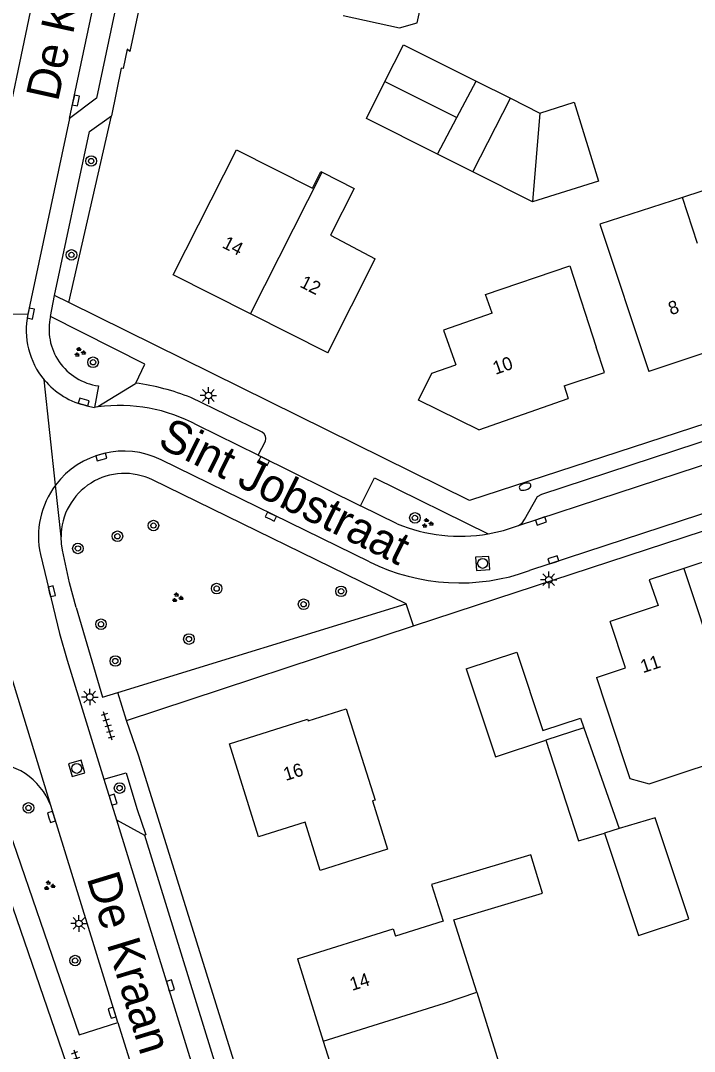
# Model space of a CAD drawing. Extents: x 136000 to 138005, y 398500 to 400500.
# Drawn here: x 137480.9 to 137531.8, y 398977.7 to 399055.6 of the extents above; entities that cross this region are included whole.
import ezdxf

# ---------------------------------------------------------------- set-up
doc = ezdxf.new("R2010")
doc.units = 0
for name, color, linetype in [('gg-anno-huisnummerreeks BGT', 7, 'Continuous'), ('gg-anno-openbare ruimte label', 7, 'Continuous'), ('gg-bbg-bijgebouw', 7, 'Continuous'), ('gg-bbg-gedigitaliseerde bebouwing', 7, 'Continuous'), ('gg-bbg-gedigitaliseerde bijgebouw', 7, 'Continuous'), ('gg-bbg-hoofdgebouw', 7, 'Continuous'), ('gg-bbg-tussenscheiding', 7, 'Continuous'), ('gg-knt-verharding', 7, 'Continuous'), ('gg-knt-verharding nz', 7, 'Continuous'), ('gt-grn-groengrens', 7, 'Continuous'), ('gt-grn-weggrens', 7, 'Continuous'), ('gt-symb-boom', 7, 'Continuous'), ('gt-symb-brandkraan', 7, 'Continuous'), ('gt-symb-groenvak', 7, 'Continuous'), ('gt-symb-kolk', 7, 'Continuous'), ('gt-symb-lichtmast', 7, 'Continuous'), ('gt-symb-rioolschacht', 7, 'Continuous'), ('gt-symb-tegel verharding', 7, 'Continuous')]:
    doc.layers.add(name, color=color, linetype=linetype)

# ---------------------------------------------------------------- blocks, each defined once
blk = doc.blocks.new('gt0-BOOM')
at = {"layer": 'gt-symb-boom'}
for radius in [0.4, 0.2]:
    blk.add_circle((0, 0), radius, dxfattribs=at)
blk = doc.blocks.new('gt0-KOLK')
at = {"layer": 'gt-symb-kolk'}
blk.add_lwpolyline([(0, 0), (0.375, 0), (0.375, 0.4), (-0.375, 0.4), (-0.375, 0), (0, 0)], dxfattribs=at)
blk = doc.blocks.new('gt0-LMAST')
at = {"layer": 'gt-symb-lichtmast'}
for p, q in [((-0.182, 0.173), (-0.447, 0.438)), ((-0.005, 0.246), (-0.005, 0.621)), ((0.172, 0.173), (0.437, 0.438)), ((-0.255, -0.004), (-0.63, -0.004)), ((-0.182, -0.181), (-0.447, -0.446)), ((-0.005, -0.254), (-0.005, -0.629)), ((0.437, -0.446), (0.172, -0.181)), ((0.245, -0.004), (0.62, -0.004))]:
    blk.add_line(p, q, dxfattribs=at)
blk.add_circle((-0.005, -0.004), 0.25, dxfattribs=at)
blk = doc.blocks.new('gt0-GRVAK')
at = {"layer": 'gt-symb-groenvak'}
for p, q in [((-0.11, 0.189), (-0.228, 0.24)), ((-0.182, 0.153), (0.088, 0.153)), ((-0.091, 0.211), (-0.156, 0.322)), ((-0.047, 0.214), (-0.047, 0.393)), ((-0.004, 0.211), (0.061, 0.322)), ((0.015, 0.189), (0.133, 0.24)), ((0.262, -0.052), (0.197, 0.059)), ((0.305, -0.049), (0.305, 0.13)), ((0.349, -0.052), (0.414, 0.059)), ((-0.245, -0.228), (-0.363, -0.177)), ((-0.318, -0.264), (-0.047, -0.264)), ((-0.226, -0.206), (-0.291, -0.095)), ((-0.183, -0.203), (-0.183, -0.024)), ((-0.139, -0.206), (-0.074, -0.095)), ((-0.12, -0.228), (-0.002, -0.177)), ((0.243, -0.074), (0.125, -0.023)), ((0.17, -0.11), (0.441, -0.11)), ((0.368, -0.074), (0.486, -0.023))]:
    blk.add_line(p, q, dxfattribs=at)
blk = doc.blocks.new('gt0-RS')
at = {"layer": 'gt-symb-rioolschacht'}
blk.add_lwpolyline([(-0.5, -0.5), (0.5, -0.5), (0.5, 0.5), (-0.5, 0.5)], close=True, dxfattribs=at)
blk.add_circle((0, 0), 0.375, dxfattribs=at)
blk = doc.blocks.new('gt0-BR')
at = {"layer": 'gt-symb-brandkraan'}
for centre, radius, start, end in [((-0.244, 0), 0.206, 107.56694, 252.43307), ((0.599, -2.664), 3, 106.89205, 107.56694), ((0, -0.691), 0.938, 73.10799, 106.89205), ((-0.599, -2.664), 3, 72.43309, 73.10799), ((0.244, 0), 0.206, 287.56695, 72.43309), ((0.599, 2.664), 3, 252.43307, 253.10797), ((0, 0.691), 0.938, 253.10797, 286.89206), ((-0.599, 2.664), 3, 286.89206, 287.56695)]:
    blk.add_arc(centre, radius, start, end, dxfattribs=at)
blk = doc.blocks.new('gt0-TEG1')
at = {"layer": 'gt-symb-tegel verharding'}
for p, q in [((-1.125, 0), (1.125, 0)), ((-0.9, -0.25), (-0.9, 0.25)), ((-0.45, -0.25), (-0.45, 0.25)), ((0, -0.25), (0, 0.25)), ((0.45, -0.25), (0.45, 0.25)), ((0.9, -0.25), (0.9, 0.25))]:
    blk.add_line(p, q, dxfattribs=at)

msp = doc.modelspace()

# ---------------------------------------------------------------- linework, layer by layer
at = {"layer": 'gg-bbg-bijgebouw'}
msp.add_line((137514.56, 399006.621), (137518.378, 399007.874), dxfattribs=at)
msp.add_lwpolyline([(137518.378, 399007.874), (137520.34, 399001.94), (137523.197, 399002.889)], dxfattribs=at)
at = {"layer": 'gg-bbg-gedigitaliseerde bebouwing'}
for p, q in [((137503.55, 399044.221), (137503.664, 399044.163)), ((137530.899, 399042.268), (137524.662, 399040.235)), ((137524.662, 399040.235), (137528.37, 399029.111)), ((137524.408, 399005.965), (137526.525, 398999.532)), ((137515.35, 398982.164), (137517.126, 398976.486))]:
    msp.add_line(p, q, dxfattribs=at)
for points in [[(137505.242, 399056.018), (137509.517, 399055.101), (137510.848, 399055.474), (137511.319, 399057.673), (137511.193, 399057.864)], [(137503.664, 399044.163), (137506.082, 399042.935), (137504.289, 399039.404), (137507.67, 399037.622)], [(137536.358, 399040.191), (137535.222, 399043.677), (137530.899, 399042.268)], [(137526.525, 398999.532), (137526.925, 398998.326), (137528.402, 398997.916), (137535.603, 399000.302), (137534.936, 399002.315)], [(137515.35, 398982.164), (137513.628, 398987.622), (137520.318, 398989.641), (137519.453, 398992.545), (137511.931, 398990.306), (137512.806, 398987.534), (137509.212, 398986.4)], [(137501.79, 398984.68), (137509.034, 398986.964), (137509.212, 398986.4)]]:
    msp.add_lwpolyline(points, dxfattribs=at)
at = {"layer": 'gg-bbg-gedigitaliseerde bijgebouw'}
for p, q in [((137515.311, 399051.055), (137517.897, 399049.758)), ((137517.897, 399049.758), (137520.113, 399048.647)), ((137515.046, 399044.2), (137512.378, 399045.538)), ((137519.557, 399041.938), (137515.046, 399044.2)), ((137523.197, 399002.889), (137523.454, 399002.156)), ((137523.454, 399002.156), (137526.123, 398994.53))]:
    msp.add_line(p, q, dxfattribs=at)
for points in [[(137508.404, 399051.025), (137509.804, 399053.816), (137515.311, 399051.055)], [(137512.378, 399045.538), (137507.004, 399048.233), (137508.404, 399051.025)], [(137520.113, 399048.647), (137522.717, 399049.457), (137524.57, 399043.497), (137519.557, 399041.938)], [(137514.56, 399006.621), (137516.76, 398999.965), (137520.574, 399001.217)], [(137520.574, 399001.217), (137523.052, 398993.616), (137525.013, 398994.199)], [(137525.013, 398994.199), (137527.59, 398986.446), (137531.384, 398987.707), (137528.847, 398995.34), (137526.123, 398994.53)]]:
    msp.add_lwpolyline(points, dxfattribs=at)
at = {"layer": 'gg-bbg-hoofdgebouw'}
for p, q in [((137504.08, 399030.501), (137507.67, 399037.622)), ((137504.08, 399030.501), (137498.24, 399033.461)), ((137534.59, 399031.176), (137528.37, 399029.111)), ((137521.956, 399028.011), (137522.27, 399027.061)), ((137515.5, 399024.691), (137522.27, 399027.061)), ((137498.85, 398993.91), (137496.66, 399000.941)), ((137501.79, 398984.68), (137503.74, 398978.469))]:
    msp.add_line(p, q, dxfattribs=at)
for points in [[(137498.24, 399033.461), (137492.4, 399036.421), (137497.19, 399045.871), (137502.92, 399042.971), (137503.55, 399044.221)], [(137516.506, 399033.511), (137516.022, 399034.929), (137522.388, 399037.098), (137524.38, 399030.948)], [(137516.506, 399033.511), (137512.85, 399032.231), (137513.772, 399029.608)], [(137521.956, 399028.011), (137525.005, 399029.017), (137524.38, 399030.948)], [(137515.5, 399024.691), (137510.945, 399026.939), (137511.945, 399028.966), (137513.772, 399029.608)], [(137537.868, 399014.31), (137534.252, 399013.202), (137533.596, 399015.071), (137531.012, 399014.21)], [(137531.012, 399014.21), (137528.386, 399013.335), (137529.066, 399011.393), (137525.437, 399010.199)], [(137524.408, 399005.965), (137526.593, 399006.684), (137525.437, 399010.199)], [(137496.66, 399000.941), (137502.562, 399002.797), (137502.595, 399002.692), (137505.484, 399003.6), (137507.66, 398996.681), (137507.468, 398996.62), (137508.615, 398992.973), (137503.519, 398991.371), (137502.372, 398995.018), (137498.85, 398993.91)], [(137503.74, 398978.469), (137505.692, 398972.252), (137512.958, 398974.533), (137512.889, 398974.753), (137515.757, 398975.654)]]:
    msp.add_lwpolyline(points, dxfattribs=at)
at = {"layer": 'gg-bbg-tussenscheiding'}
for p, q in [((137508.404, 399051.025), (137513.844, 399048.297)), ((137513.844, 399048.297), (137515.311, 399051.055)), ((137515.046, 399044.2), (137517.897, 399049.758)), ((137512.378, 399045.538), (137513.844, 399048.297)), ((137520.113, 399048.647), (137519.557, 399041.938)), ((137498.24, 399033.461), (137503.664, 399044.163)), ((137532.052, 399038.788), (137530.899, 399042.268)), ((137531.012, 399014.21), (137534.936, 399002.315)), ((137523.454, 399002.156), (137520.574, 399001.217)), ((137526.123, 398994.53), (137525.013, 398994.199))]:
    msp.add_line(p, q, dxfattribs=at)
msp.add_lwpolyline([(137503.74, 398978.469), (137512.912, 398981.335), (137515.35, 398982.164)], dxfattribs=at)
at = {"layer": 'gg-knt-verharding'}
for p, q in [((137479.154, 399044.724), (137482.865, 399062.215)), ((137484.549, 399048.243), (137481.41, 399033.428)), ((137594.446, 399038.703), (137519.344, 399014.042)), ((137484.498, 399034.318), (137483.428, 399034.847)), ((137486.738, 399028.014), (137486.436, 399026.386)), ((137485.874, 399026.51), (137486.436, 399026.386)), ((137486.705, 399026.425), (137486.436, 399026.386)), ((137499.132, 399024.519), (137493.743, 399027.134)), ((137498.828, 399022.763), (137494.215, 399025.036)), ((137498.828, 399022.763), (137499.367, 399023.837)), ((137498.828, 399022.763), (137506.568, 399018.949)), ((137507.232, 399014.699), (137491.48, 399022.423)), ((137510.009, 399011.531), (137490.836, 399020.895)), ((137509.333, 399017.587), (137506.568, 399018.949)), ((137485.057, 399011.265), (137484.562, 399013.109)), ((137488.208, 399004.817), (137510.009, 399011.531)), ((137488.857, 399002.709), (137510.559, 399009.861)), ((137477.121, 398997.647), (137489.641, 398961.324)), ((137487.154, 398998.26), (137488.105, 398995.186)), ((137488.211, 398979.877), (137483.136, 398996.273)), ((137488.105, 398995.186), (137498.482, 398961.63)), ((137488.105, 398995.186), (137490.215, 398994.036)), ((137490.215, 398994.036), (137499.586, 398963.729)), ((137488.211, 398979.877), (137489.6, 398975.393))]:
    msp.add_line(p, q, dxfattribs=at)
for points in [[(137510.405, 399153.353), (137504.79, 399126.13), (137504.64, 399126.151), (137489.12, 399053.301), (137488.92, 399053.471), (137488.609, 399052.017), (137488.466, 399052.04), (137487.721, 399048.445)], [(137493.294, 399081.45), (137486.6, 399049.76), (137484.549, 399048.243)], [(137483.428, 399034.847), (137486.061, 399047.262), (137487.721, 399048.445)], [(137593.247, 399044.904), (137514.814, 399019.342), (137484.498, 399034.318)], [(137510.559, 399009.861), (137516.87, 399011.941), (137577.85, 399031.891), (137594.78, 399037.492)], [(137518.519, 399017.445), (137518.783, 399017.635), (137518.968, 399017.901), (137519.936, 399019.642), (137520.269, 399019.833), (137567.415, 399035.293)], [(137489.569, 399028.227), (137490.264, 399029.659), (137483.116, 399033.267)], [(137489.569, 399028.227), (137489.536, 399028.16), (137486.705, 399026.425)], [(137506.568, 399018.949), (137507.62, 399021.049), (137516.216, 399016.824)], [(137516.216, 399016.824), (137517.367, 399017.076), (137518.519, 399017.445)], [(137484.562, 399013.109), (137484.028, 399015.576), (137483.947, 399016.078), (137483.919, 399016.591)], [(137482.362, 399015.26), (137483.798, 399009.275), (137484.369, 399007.263), (137487.154, 398998.26)], [(137485.057, 399011.265), (137487.048, 399004.46), (137488.208, 399004.817)], [(137518.887, 398902.889), (137509.25, 398932.72), (137510.31, 398933.07), (137509.35, 398936.24), (137509.65, 398936.32), (137489.786, 399000), (137488.857, 399002.709)], [(137478.212, 398999.497), (137485.275, 398978.941), (137488.211, 398979.877)], [(137487.154, 398998.26), (137488.833, 398998.745), (137489.654, 398996.054), (137490.33, 398994.071), (137490.215, 398994.036)]]:
    msp.add_lwpolyline(points, dxfattribs=at)
for centre, radius, start, end in [((137487.125, 399032.217), 5.842, 168.04017, 219.93991), ((137487.329, 399032.296), 4.323, 167.02615, 262.14721), ((137487.127, 399032.217), 5.843, 219.92702, 257.61965), ((137486.82, 399009.214), 19.211, 68.87814, 81.77396), ((137488.325, 399014.189), 12.343, 61.49929, 97.54344), ((137498.841, 399024.037), 0.563, 339.15416, 58.87116), ((137488.647, 399016.644), 6.436, 63.88234, 143.11673), ((137488.716, 399016.592), 4.797, 63.774, 180.00864), ((137488.648, 399016.644), 6.437, 143.12673, 192.4199), ((137514.105, 399029.212), 12.567, 247.68037, 279.66849), ((137514.059, 399028.583), 15.471, 243.81537, 289.97484), ((137478.474, 398994.525), 4.979, 20.55494, 93.01533)]:
    msp.add_arc(centre, radius, start, end, dxfattribs=at)
at = {"layer": 'gg-knt-verharding nz'}
for p, q in [((137484.549, 399048.243), (137492.113, 399083.938)), ((137518.519, 399017.445), (137568.892, 399034.003))]:
    msp.add_line(p, q, dxfattribs=at)
at = {"layer": 'gt-grn-groengrens'}
msp.add_line((137484.498, 399034.318), (137487.721, 399048.445), dxfattribs=at)
at = {"layer": 'gt-grn-weggrens'}
for p, q in [((137483.116, 399033.267), (137483.428, 399034.847)), ((137481.41, 399033.428), (137473.311, 399033.317)), ((137483.499, 399020.507), (137482.646, 399028.467)), ((137483.919, 399016.591), (137483.499, 399020.507)), ((137510.559, 399009.861), (137510.009, 399011.531)), ((137483.136, 398996.273), (137478.79, 399010.485)), ((137488.857, 399002.709), (137488.208, 399004.817))]:
    msp.add_line(p, q, dxfattribs=at)

# ---------------------------------------------------------------- block references
at = {"layer": 'gt-symb-boom'}
for p in [(137486.196, 399045.016), (137484.704, 399037.918), (137486.337, 399029.797), (137490.903, 399017.45), (137510.679, 399018.029), (137488.18, 399016.639), (137485.192, 399015.718), (137495.683, 399012.682), (137505.092, 399012.477), (137502.258, 399011.497), (137486.938, 399009.986), (137493.587, 399008.867), (137488.019, 399007.204), (137488.345, 398997.597), (137481.455, 398996.096), (137484.979, 398984.554)]:
    msp.add_blockref('gt0-BOOM', p, dxfattribs=at)
at = {"layer": 'gt-symb-brandkraan', "rotation": 16.441280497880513}
msp.add_blockref('gt0-BR', (137519.005, 399020.392), dxfattribs=at)
at = {"layer": 'gt-symb-groenvak'}
for p in [(137485.323, 399030.558), (137511.609, 399017.619), (137492.701, 399011.993), (137483.016, 398990.214)]:
    msp.add_blockref('gt0-GRVAK', p, dxfattribs=at)
at = {"layer": 'gt-symb-kolk'}
for p, rotation in [((137485.236, 399049.555), 78.04935273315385), ((137481.826, 399033.436), 78.22937399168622), ((137485.583, 399026.595), -15.481185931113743), ((137487.018, 399022.446), 15.245070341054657), ((137499.175, 399022.149), -26.231939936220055), ((137499.694, 399017.948), -25.975714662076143), ((137520.272, 399017.602), 18.235691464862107), ((137521.207, 399014.666), 18.000074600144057), ((137483.028, 399012.437), -76.22785456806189), ((137487.656, 398996.662), -72.72457972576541), ((137483.001, 398995.356), -73.01526746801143), ((137491.993, 398982.608), -72.83405394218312), ((137487.584, 398980.544), -72.83405393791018)]:
    msp.add_blockref('gt0-KOLK', p, dxfattribs=dict(at, rotation=rotation))
at = {"layer": 'gt-symb-lichtmast'}
for p in [(137495.064, 399027.289), (137520.8, 399013.351), (137486.097, 399004.487), (137485.277, 398987.364)]:
    msp.add_blockref('gt0-LMAST', p, dxfattribs=at)
at = {"layer": 'gt-symb-rioolschacht'}
for p, rotation in [((137515.795, 399014.588), 4.012171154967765), ((137485.101, 398999.086), -73.9758903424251)]:
    msp.add_blockref('gt0-RS', p, dxfattribs=dict(at, rotation=rotation))
at = {"layer": 'gt-symb-tegel verharding'}
for p, rotation in [((137487.456, 399002.292), 107.22069937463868), ((137485.238, 398976.74), -70.96692019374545)]:
    msp.add_blockref('gt0-TEG1', p, dxfattribs=dict(at, rotation=rotation))

# ---------------------------------------------------------------- texts
at = {"layer": 'gg-anno-huisnummerreeks BGT'}
for s, rotation, p in [('14', 333.1, (137496.031, 399038.505)), ('12', 333.1, (137501.9, 399035.531)), ('8', 18.4, (137530.03, 399033.349)), ('10', 19.3, (137516.772, 399028.844)), ('11', 18.2, (137527.922, 399006.279)), ('16', 17.3, (137500.91, 398998.132)), ('14', 17.5, (137505.93, 398982.254))]:
    msp.add_text(s, height=1, rotation=rotation, dxfattribs=at).set_placement(p)
at = {"layer": 'gg-anno-openbare ruimte label'}
for s, rotation, p in [('De Kraan', 77.5, (137483.679, 399049.453)), ('Sint Jobstraat', 333.7, (137491.125, 399023.468)), ('De Kraan', 287, (137485.838, 398990.797))]:
    msp.add_text(s, height=2.5, rotation=rotation, dxfattribs=at).set_placement(p)

doc.saveas('drawing.dxf')
